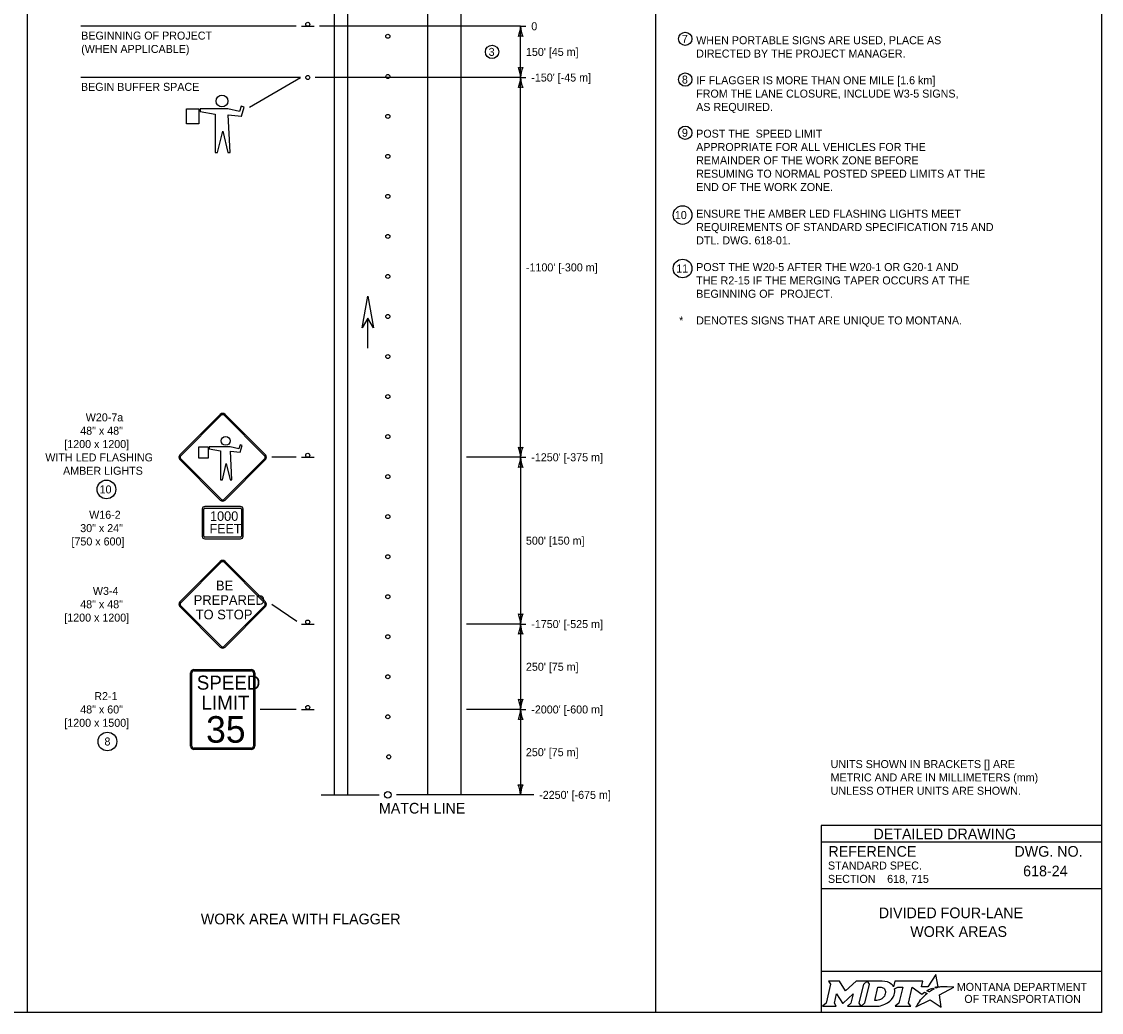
# Model space of a CAD drawing. Extents: x 49991.4 to 50021, y 49987.6 to 50011.4.
# Drawn here: x 50008.66 to 50016.75, y 49987.8 to 49995.22 of the extents above; entities that cross this region are included whole.
import ezdxf

# ---------------------------------------------------------------- set-up
doc = ezdxf.new("R2010")
doc.units = 0
for name, color, linetype in [('Default', 7, 'Continuous'), ('Level 1', 7, 'Continuous'), ('Level 2', 7, 'Continuous'), ('Level 3', 7, 'Continuous'), ('Level 5', 7, 'Continuous'), ('Level 6', 7, 'Continuous')]:
    doc.layers.add(name, color=color, linetype=linetype)

msp = doc.modelspace()

# ---------------------------------------------------------------- linework, layer by layer
at = {"layer": 'Default'}
for points in [[(50014.7056, 49988.0338), (50014.7197, 49988.0104), (50014.6862, 49987.8671), (50014.6605, 49987.8446), (50014.7621, 49987.8446), (50014.7486, 49987.8674), (50014.7648, 49987.9375), (50014.8085, 49987.8685), (50014.8138, 49987.8685), (50014.8889, 49987.938), (50014.8725, 49987.8669), (50014.8478, 49987.8449), (50014.9494, 49987.8449), (50014.9356, 49987.8682), (50014.9688, 49988.0106)], [(50014.9688, 49988.0106), (50014.9941, 49988.0338), (50014.9117, 49988.0338), (50014.8321, 49987.9608), (50014.7876, 49988.0335), (50014.7056, 49988.0338)], [(50015.1077, 49988.0338), (50014.9941, 49988.0338), (50015.0088, 49988.0109), (50014.9749, 49987.8671), (50014.9494, 49987.8449), (50015.06, 49987.8449)], [(50015.5126, 49987.9811), (50015.5023, 49987.9867), (50015.5139, 49987.9895), (50015.5255, 49987.9915), (50015.5081, 49988.0816), (50015.4486, 49987.9903), (50015.4013, 49987.9896), (50015.4116, 49988.0337), (50015.2024, 49988.0338), (50015.1923, 49987.9913), (50015.1865, 49987.9996)], [(50015.1317, 49987.9471), (50015.1305, 49987.939), (50015.1273, 49987.9297), (50015.1231, 49987.9215), (50015.1175, 49987.914), (50015.111, 49987.9071), (50015.1031, 49987.9008), (50015.0948, 49987.8961), (50015.0857, 49987.8922), (50015.0766, 49987.8899), (50015.0674, 49987.889), (50015.0515, 49987.889), (50015.0751, 49987.989), (50015.0911, 49987.989), (50015.0987, 49987.9884), (50015.1063, 49987.9865), (50015.1129, 49987.9835), (50015.119, 49987.9793), (50015.1238, 49987.9743), (50015.1275, 49987.9683), (50015.1302, 49987.9621), (50015.1318, 49987.9547), (50015.1318, 49987.9517), (50015.1317, 49987.9471)], [(50015.1991, 49987.9747), (50015.2237, 49987.9878), (50015.2606, 49987.9878), (50015.232, 49987.8673), (50015.2045, 49987.8446), (50015.3207, 49987.8446), (50015.3037, 49987.8675), (50015.3319, 49987.9877), (50015.4032, 49987.936), (50015.4243, 49987.9511), (50015.444, 49987.9402)], [(50015.3882, 49987.8843), (50015.3729, 49987.8599), (50015.3682, 49987.8524), (50015.3624, 49987.8438), (50015.3601, 49987.8395), (50015.4654, 49987.8926), (50015.5493, 49987.8375), (50015.5362, 49987.9302), (50015.6431, 49987.9886), (50015.5938, 49987.9894), (50015.5637, 49987.9898), (50015.5429, 49987.9901), (50015.5361, 49987.9886), (50015.5312, 49987.9874), (50015.5228, 49987.9851), (50015.5126, 49987.9811)], [(50015.4622, 49987.9535), (50015.4598, 49987.9518), (50015.4415, 49987.9614), (50015.4518, 49987.9671), (50015.4559, 49987.9693), (50015.4645, 49987.9733), (50015.4702, 49987.9759), (50015.4781, 49987.9789), (50015.4854, 49987.9816), (50015.4972, 49987.9742), (50015.4932, 49987.9721), (50015.4886, 49987.9696), (50015.4844, 49987.9674), (50015.4794, 49987.9645), (50015.4775, 49987.9634), (50015.4748, 49987.9618), (50015.4723, 49987.9604), (50015.47, 49987.9588), (50015.4674, 49987.957), (50015.4647, 49987.9552), (50015.4622, 49987.9535)], [(50015.1057, 49987.8522), (50015.1141, 49987.8548), (50015.1271, 49987.8602), (50015.1475, 49987.8712)], [(50015.4021, 49987.9004), (50015.4021, 49987.9004)]]:
    msp.add_lwpolyline(points, dxfattribs=at)
for centre, radius, start, end in [((50015.1308, 49987.9554), 0.0709, 339.53292, 15.85821), ((50015.0868, 49987.9727), 0.1183, 300.91025, 339.13831)]:
    msp.add_arc(centre, radius, start, end, dxfattribs=at)
for centre, major_axis, ratio, start_param, end_param in [((50015.1056, 49987.9864), (0.0834, -0.0037), 0.568097, 0.61298, 1.570796), ((50015.1612, 49987.9937), (0.0361, -0.0295), 0.469099, 1.225588, 1.570796), ((50015.3952, 49987.8923), (-0.00694, -0.00806), 0.008222, 0, 3.137361), ((50015.4119, 49987.9106), (-0.0098, -0.0102), 0.016458, 3.141593, 6.279097), ((50015.4329, 49987.9305), (-0.0112, -0.0097), 0.021651, 3.157348, 6.283185), ((50015.0603, 49987.9932), (0, 0.1484), 0.987302, 3.139398, 3.456847)]:
    msp.add_ellipse(centre, major_axis=major_axis, ratio=ratio, start_param=start_param, end_param=end_param, dxfattribs=at)
at = {"layer": 'Level 1'}
for p, q in [((50011.0016, 49989.429), (50011.0016, 49998.194)), ((50011.1016, 49989.429), (50011.1016, 49998.194)), ((50011.7016, 49989.429), (50011.7016, 49998.194)), ((50011.9516, 49989.429), (50011.9516, 49998.194)), ((50010.7536, 49995.189), (50010.8496, 49995.189)), ((50010.3015, 49994.5895), (50010.2888, 49994.5499)), ((50010.3235, 49994.584), (50010.3015, 49994.5895)), ((50010.3035, 49994.5152), (50010.3235, 49994.584)), ((50009.8929, 49994.4581), (50009.8929, 49994.5706)), ((50009.8929, 49994.5706), (50009.9848, 49994.5706)), ((50009.9848, 49994.5706), (50009.9848, 49994.4581)), ((50010.202, 49994.5699), (50009.9951, 49994.5699)), ((50009.9951, 49994.5699), (50009.9951, 49994.5513)), ((50009.9951, 49994.5513), (50010.1076, 49994.5291)), ((50010.1076, 49994.5291), (50010.1076, 49994.2428)), ((50010.2888, 49994.5499), (50010.202, 49994.5699)), ((50010.2207, 49994.2428), (50010.2059, 49994.5262)), ((50010.2059, 49994.5262), (50010.3035, 49994.5152)), ((50009.9848, 49994.4581), (50009.8929, 49994.4581)), ((50010.1258, 49994.2428), (50010.1641, 49994.4041)), ((50010.1641, 49994.4041), (50010.2024, 49994.2428)), ((50010.1076, 49994.2428), (50010.1258, 49994.2428)), ((50010.2024, 49994.2428), (50010.2207, 49994.2428)), ((50011.2516, 49992.776), (50011.2516, 49993.0019)), ((50011.2519, 49992.776), (50011.2519, 49993.0019)), ((50010.1459, 49992.2807), (50009.8418, 49991.9767)), ((50010.1529, 49992.2737), (50009.8489, 49991.9696)), ((50010.4782, 49991.9696), (50010.1742, 49992.2737)), ((50010.4853, 49991.9767), (50010.1812, 49992.2807)), ((50009.9852, 49991.953), (50009.9852, 49992.038)), ((50009.9852, 49992.038), (50010.0547, 49992.038)), ((50010.0547, 49992.038), (50010.0547, 49991.953)), ((50010.219, 49992.0376), (50010.0625, 49992.0376)), ((50010.0625, 49992.0376), (50010.0625, 49992.0235)), ((50010.0625, 49992.0235), (50010.1475, 49992.0067)), ((50010.1475, 49992.0067), (50010.1475, 49991.7902)), ((50010.2846, 49992.0224), (50010.219, 49992.0376)), ((50010.233, 49991.7902), (50010.2218, 49992.0045)), ((50010.2218, 49992.0045), (50010.2957, 49991.9962)), ((50010.2942, 49992.0524), (50010.2846, 49992.0224)), ((50010.3108, 49992.0482), (50010.2942, 49992.0524)), ((50010.2957, 49991.9962), (50010.3108, 49992.0482)), ((50009.8418, 49991.9413), (50010.1459, 49991.6373)), ((50009.8489, 49991.9484), (50010.1529, 49991.6443)), ((50010.0547, 49991.953), (50009.9852, 49991.953)), ((50010.1613, 49991.7902), (50010.1902, 49991.9122)), ((50010.1742, 49991.6443), (50010.4782, 49991.9484)), ((50010.1812, 49991.6373), (50010.4853, 49991.9413)), ((50010.1902, 49991.9122), (50010.2192, 49991.7902)), ((50010.7534, 49991.959), (50010.8494, 49991.959)), ((50010.1475, 49991.7902), (50010.1613, 49991.7902)), ((50010.2192, 49991.7902), (50010.233, 49991.7902)), ((50010.2976, 49991.5899), (50010.0295, 49991.5899)), ((50010.0103, 49991.5698), (50010.0103, 49991.3682)), ((50010.0231, 49991.3682), (50010.0231, 49991.5698)), ((50010.0295, 49991.5765), (50010.2976, 49991.5765)), ((50010.304, 49991.5698), (50010.304, 49991.3682)), ((50010.3168, 49991.3682), (50010.3168, 49991.5698)), ((50010.2976, 49991.3615), (50010.0295, 49991.3615)), ((50010.0295, 49991.348), (50010.2976, 49991.348)), ((50009.8418, 49990.875), (50010.1459, 49991.179)), ((50009.8489, 49990.8679), (50010.1529, 49991.172)), ((50010.1742, 49991.172), (50010.4782, 49990.8679)), ((50010.1812, 49991.179), (50010.4853, 49990.875)), ((50010.1459, 49990.5356), (50009.8418, 49990.8396)), ((50010.1529, 49990.5426), (50009.8489, 49990.8467)), ((50010.4782, 49990.8467), (50010.1742, 49990.5426)), ((50010.4853, 49990.8396), (50010.1812, 49990.5356)), ((50010.7534, 49990.709), (50010.8494, 49990.709)), ((50009.9236, 49989.794), (50009.9236, 49990.344)), ((50009.9336, 49989.794), (50009.9336, 49990.344)), ((50009.9486, 49990.369), (50010.3786, 49990.369)), ((50009.9486, 49990.359), (50010.3786, 49990.359)), ((50010.3936, 49990.344), (50010.3936, 49989.794)), ((50010.4036, 49990.344), (50010.4036, 49989.794)), ((50010.7536, 49990.069), (50010.8496, 49990.069)), ((50010.3786, 49989.779), (50009.9486, 49989.779)), ((50010.3786, 49989.769), (50009.9486, 49989.769))]:
    msp.add_line(p, q, dxfattribs=at)
for points in [[(49999.3835, 49998.9992), (50016.7501, 49998.9992), (50016.7501, 49987.7988), (49999.3835, 49987.7988)], [(50011.2099, 49992.9296), (50011.2516, 49993.1661), (50011.2935, 49992.9296), (50011.2516, 49993.0018)]]:
    msp.add_lwpolyline(points, close=True, dxfattribs=at)
for points in [[(50010.3014, 49994.5893), (50010.3016, 49994.5895)], [(50010.3029, 49994.5153), (50010.3038, 49994.5164)], [(50009.9844, 49994.4581), (50009.9848, 49994.4585)], [(50010.2941, 49992.0522), (50010.2942, 49992.0524)], [(50010.2952, 49991.9963), (50010.2959, 49991.9971)], [(50010.0544, 49991.953), (50010.0547, 49991.9533)]]:
    msp.add_lwpolyline(points, dxfattribs=at)
for centre, radius in [((50010.8016, 49995.2042), 0.0152), ((50011.4016, 49995.114), 0.015), ((50011.4021, 49994.8126), 0.015), ((50010.8016, 49994.805), 0.0152), ((50010.1584, 49994.6287), 0.0442), ((50011.4016, 49994.514), 0.015), ((50011.4016, 49994.214), 0.015), ((50011.4016, 49993.914), 0.015), ((50011.4016, 49993.614), 0.015), ((50011.4016, 49993.314), 0.015), ((50011.4016, 49993.014), 0.015), ((50011.4016, 49992.714), 0.015), ((50011.4016, 49992.414), 0.015), ((50010.186, 49992.082), 0.0334), ((50011.4016, 49992.114), 0.015), ((50010.8014, 49991.9742), 0.0152), ((50011.4016, 49991.814), 0.015), ((50011.4016, 49991.514), 0.015), ((50011.4016, 49991.214), 0.015), ((50011.4016, 49990.914), 0.015), ((50010.8014, 49990.7242), 0.0152), ((50011.4016, 49990.614), 0.015), ((50011.4016, 49990.314), 0.015), ((50010.8016, 49990.0842), 0.0152), ((50011.4016, 49990.014), 0.015), ((50011.4086, 49989.714), 0.015), ((50011.4016, 49989.429), 0.025)]:
    msp.add_circle(centre, radius, dxfattribs=at)
for centre, radius, start, end in [((50010.1636, 49992.2631), 0.025, 45, 135), ((50010.1636, 49992.2631), 0.015, 45, 135), ((50009.8595, 49991.959), 0.025, 135, 225), ((50009.8595, 49991.959), 0.015, 135, 225), ((50010.4676, 49991.959), 0.015, 315, 45.00024), ((50010.4676, 49991.959), 0.025, 315, 45.00024), ((50010.1636, 49991.6549), 0.025, 225, 314.99957), ((50010.1636, 49991.6549), 0.015, 225, 314.99957), ((50010.1635, 49991.1614), 0.025, 45, 135), ((50010.1635, 49991.1614), 0.015, 45, 135), ((50009.8595, 49990.8574), 0.025, 134.99976, 225), ((50009.8595, 49990.8574), 0.015, 134.99976, 225), ((50010.4676, 49990.8574), 0.015, 315, 45), ((50010.4676, 49990.8574), 0.025, 315, 45), ((50010.1635, 49990.5533), 0.025, 225.00043, 315), ((50010.1635, 49990.5533), 0.015, 225.00043, 315), ((50009.9486, 49990.344), 0.025, 90, 180), ((50009.9486, 49990.344), 0.015, 90, 180), ((50010.3786, 49990.344), 0.025, 0, 90), ((50010.3786, 49990.344), 0.015, 0, 90), ((50009.9486, 49989.794), 0.025, 180, 270), ((50009.9486, 49989.794), 0.015, 180, 270), ((50010.3786, 49989.794), 0.025, 270, 0), ((50010.3786, 49989.794), 0.015, 270, 0)]:
    msp.add_arc(centre, radius, start, end, dxfattribs=at)
for centre, major_axis, start_param, end_param in [((50010.0295, 49991.5698), (0, 0.0202), 0, 1.570796), ((50010.2976, 49991.5698), (0, 0.0202), 4.712389, 6.283185), ((50010.0295, 49991.5698), (0, 0.00672), 0, 1.570796), ((50010.2976, 49991.5698), (0, 0.00672), 4.712389, 6.283185), ((50010.0295, 49991.3682), (0, -0.0202), 4.712389, 6.283185), ((50010.0295, 49991.3682), (0, -0.00672), 4.712389, 6.283185), ((50010.2976, 49991.3682), (0, -0.00672), 0, 1.570796), ((50010.2976, 49991.3682), (0, -0.0202), 0, 1.570796)]:
    msp.add_ellipse(centre, major_axis=major_axis, ratio=0.95, start_param=start_param, end_param=end_param, dxfattribs=at)
at = {"layer": 'Level 2'}
for centre, radius in [((50013.631, 49995.0948), 0.05), ((50012.1824, 49994.997), 0.05), ((50013.631, 49994.7897), 0.05), ((50013.631, 49994.3911), 0.05), ((50013.611, 49993.7743), 0.07), ((50013.611, 49993.3737), 0.07), ((50009.2924, 49991.7181), 0.07), ((50009.2996, 49989.829), 0.07)]:
    msp.add_circle(centre, radius, dxfattribs=at)
at = {"layer": 'Level 3'}
for p, q in [((50008.6982, 49998.9992), (50008.6982, 49987.7988)), ((50013.4076, 49998.9992), (50013.4076, 49987.7988)), ((50010.7136, 49995.189), (50009.1014, 49995.189)), ((50012.3968, 49995.189), (50010.8896, 49995.189)), ((50012.3968, 49994.805), (50012.3968, 49995.189)), ((50012.3968, 49995.189), (50012.4368, 49995.189)), ((50010.7463, 49994.805), (50009.1014, 49994.805)), ((50010.3635, 49994.584), (50010.7463, 49994.805)), ((50012.3968, 49994.805), (50010.8568, 49994.805)), ((50012.3968, 49991.959), (50012.3968, 49994.805)), ((50012.3968, 49994.805), (50012.4368, 49994.805)), ((50010.7134, 49991.959), (50010.5326, 49991.959)), ((50012.3968, 49991.959), (50011.9916, 49991.959)), ((50012.3968, 49991.959), (50012.3968, 49990.709)), ((50012.3968, 49991.959), (50012.4368, 49991.959)), ((50010.5326, 49990.8574), (50010.7202, 49990.7313)), ((50012.3968, 49990.709), (50011.9916, 49990.709)), ((50012.3968, 49990.709), (50012.3968, 49990.069)), ((50012.3968, 49990.709), (50012.4368, 49990.709)), ((50010.7136, 49990.069), (50010.4436, 49990.069)), ((50012.3968, 49990.069), (50011.9916, 49990.069)), ((50012.3968, 49990.069), (50012.396, 49989.429)), ((50012.3968, 49990.069), (50012.4368, 49990.069))]:
    msp.add_line(p, q, dxfattribs=at)
for centre, radius, start, end in [((50012.1641, 49995.2005), 0.233, 337.92284, 357.17269), ((50012.6189, 49995.1982), 0.2223, 182.36048, 202.54399), ((50012.3968, 49995.0608), 0.0548, 72.13882, 107.86118), ((50012.3968, 49994.9332), 0.0548, 252.13882, 287.86118), ((50012.1641, 49994.7935), 0.233, 2.82731, 22.07716), ((50012.6189, 49994.7958), 0.2223, 157.45601, 177.63952), ((50012.1641, 49994.8165), 0.233, 337.92284, 357.17269), ((50012.6189, 49994.8142), 0.2223, 182.36048, 202.54399), ((50012.3968, 49994.6768), 0.0548, 72.13882, 107.86118), ((50012.1747, 49991.9498), 0.2223, 2.36048, 22.54399), ((50012.3968, 49992.0872), 0.0548, 252.13882, 287.86118), ((50012.6295, 49991.9475), 0.233, 157.92284, 177.17269), ((50012.1747, 49991.9682), 0.2223, 337.45601, 357.63952), ((50012.6295, 49991.9705), 0.233, 182.82731, 202.07716), ((50012.3968, 49991.8308), 0.0548, 72.13882, 107.86118), ((50012.3968, 49990.8372), 0.0548, 252.13882, 287.86118), ((50012.1641, 49990.6975), 0.233, 2.82731, 22.07716), ((50012.6189, 49990.6998), 0.2223, 157.45601, 177.63952), ((50012.1747, 49990.7182), 0.2223, 337.45601, 357.63952), ((50012.6295, 49990.7205), 0.233, 182.82731, 202.07716), ((50012.3968, 49990.5808), 0.0548, 72.13882, 107.86118), ((50012.3968, 49990.1972), 0.0548, 252.13882, 287.86118), ((50012.1641, 49990.0575), 0.233, 2.82731, 22.07716), ((50012.6189, 49990.0598), 0.2223, 157.45601, 177.63952), ((50012.1747, 49990.0782), 0.2223, 337.45601, 357.63952), ((50012.6295, 49990.0805), 0.233, 182.82731, 202.07716), ((50012.3968, 49989.9408), 0.0548, 72.13882, 107.86118), ((50012.396, 49989.5572), 0.0548, 252.13882, 287.86118), ((50012.1633, 49989.4175), 0.233, 2.82731, 22.07716), ((50012.6182, 49989.4198), 0.2223, 157.45601, 177.63952)]:
    msp.add_arc(centre, radius, start, end, dxfattribs=at)
at = {"layer": 'Level 5'}
for p, q in [((50016.7501, 49989.1988), (50014.6501, 49989.1988)), ((50014.6501, 49989.1988), (50014.6501, 49987.7988)), ((50016.7501, 49989.0738), (50014.6501, 49989.0738)), ((50016.3862, 49988.8587), (50016.3862, 49988.8587)), ((50015.1444, 49988.7993), (50015.1444, 49988.7993)), ((50016.7501, 49988.7238), (50014.6501, 49988.7238)), ((50015.7001, 49988.4747), (50015.7001, 49988.4747)), ((50016.7501, 49988.1057), (50014.6501, 49988.1057))]:
    msp.add_line(p, q, dxfattribs=at)
at = {"layer": 'Level 6'}
for p, q in [((50010.9016, 49989.429), (50011.3366, 49989.429)), ((50012.496, 49989.429), (50011.4666, 49989.429))]:
    msp.add_line(p, q, dxfattribs=at)

# ---------------------------------------------------------------- texts
at = {"layer": 'Default'}
for s, p in [('MONTANA DEPARTMENT', (50015.6663, 49987.96)), ('OF TRANSPORTATION', (50015.7225, 49987.87))]:
    msp.add_text(s, height=0.06, dxfattribs=at).set_placement(p)
at = {"layer": 'Level 1'}
for s, height, p in [('1000', 0.07124, (50010.0685, 49991.4824)), ('FEET', 0.06989, (50010.0655, 49991.3883)), ('BE', 0.0725, (50010.1132, 49990.9618)), ('PREPARED', 0.0725, (50009.9463, 49990.853)), ('TO STOP', 0.0725, (50009.9611, 49990.7443)), ('SPEED', 0.10512, (50009.9698, 49990.2174)), ('LIMIT', 0.10512, (50010.0052, 49990.0673)), ('35', 0.19892, (50010.0392, 49989.82))]:
    msp.add_text(s, height=height, dxfattribs=at).set_placement(p)
at = {"layer": 'Level 2'}
for s, height, p in [('BEGINNING OF PROJECT', 0.06, (50009.1033, 49995.089)), ('0', 0.06, (50012.4768, 49995.159)), ('7', 0.06, (50013.6058, 49995.0648)), ('WHEN PORTABLE SIGNS ARE USED, PLACE AS', 0.06, (50013.7128, 49995.0544)), ('(WHEN APPLICABLE)', 0.06, (50009.1033, 49994.989)), ('3', 0.06, (50012.1572, 49994.967)), ("150' [45 m]", 0.06, (50012.4368, 49994.967)), ('DIRECTED BY THE PROJECT MANAGER.', 0.06, (50013.7128, 49994.9544)), ("-150' [-45 m]", 0.06, (50012.4768, 49994.775)), ('BEGIN BUFFER SPACE', 0.06, (50009.1014, 49994.705)), ('8', 0.06, (50013.6058, 49994.7597)), ('IF FLAGGER IS MORE THAN ONE MILE [1.6 km]', 0.06, (50013.7128, 49994.7544)), ('FROM THE LANE CLOSURE, INCLUDE W3-5 SIGNS,', 0.06, (50013.7128, 49994.6544)), ('AS REQUIRED.', 0.06, (50013.7128, 49994.5544)), ('9', 0.06, (50013.6056, 49994.3611)), ('POST THE  SPEED LIMIT', 0.06, (50013.7128, 49994.3544)), ('APPROPRIATE FOR ALL VEHICLES FOR THE ', 0.06, (50013.7128, 49994.2544)), ('REMAINDER OF THE WORK ZONE BEFORE', 0.06, (50013.7128, 49994.1544)), ('RESUMING TO NORMAL POSTED SPEED LIMITS AT THE', 0.06, (50013.7128, 49994.0544)), ('END OF THE WORK ZONE.', 0.06, (50013.7128, 49993.9544)), ('10', 0.06, (50013.5528, 49993.7443)), ('ENSURE THE AMBER LED FLASHING LIGHTS MEET', 0.06, (50013.7128, 49993.7544)), ('REQUIREMENTS OF STANDARD SPECIFICATION 715 AND ', 0.06, (50013.7128, 49993.6544)), ('DTL. DWG. 618-01.', 0.06, (50013.7128, 49993.5544)), ("-1100' [-300 m]", 0.06, (50012.4368, 49993.352)), ('11', 0.06, (50013.5631, 49993.3437)), ('POST THE W20-5 AFTER THE W20-1 OR G20-1 AND', 0.06, (50013.7128, 49993.3544)), ('THE R2-15 IF THE MERGING TAPER OCCURS AT THE', 0.06, (50013.7128, 49993.2544)), ('BEGINNING OF  PROJECT.', 0.06, (50013.7128, 49993.1544)), ('*', 0.06, (50013.5849, 49992.9544)), ('DENOTES SIGNS THAT ARE UNIQUE TO MONTANA.', 0.06, (50013.7128, 49992.9544)), ('W20-7a', 0.06, (50009.1373, 49992.2281)), ('48" x 48"', 0.06, (50009.0959, 49992.1281)), ('[1200 x 1200]', 0.06, (50008.9764, 49992.0281)), ("-1250' [-375 m]", 0.06, (50012.4768, 49991.929)), ('WITH LED FLASHING', 0.06, (50008.8342, 49991.9281)), ('AMBER LIGHTS', 0.06, (50008.9674, 49991.8281)), ('10', 0.06, (50009.2411, 49991.6881)), ('W16-2', 0.06, (50009.1628, 49991.4981)), ('30" x 24"', 0.06, (50009.0959, 49991.3981)), ('[750 x 600]', 0.06, (50009.0303, 49991.2981)), ("500' [150 m]", 0.06, (50012.4368, 49991.304)), ('W3-4', 0.06, (50009.1909, 49990.9274)), ('48" x 48"', 0.06, (50009.0959, 49990.8274)), ('[1200 x 1200]', 0.06, (50008.9764, 49990.7274)), ("-1750' [-525 m]", 0.06, (50012.4768, 49990.679)), ("250' [75 m]", 0.06, (50012.4368, 49990.359)), ('R2-1', 0.06, (50009.2014, 49990.139)), ('48" x 60"', 0.06, (50009.0959, 49990.039)), ("-2000' [-600 m]", 0.06, (50012.4768, 49990.039)), ('[1200 x 1500]', 0.06, (50008.9764, 49989.939)), ('8', 0.06, (50009.2774, 49989.799)), ("250' [75 m]", 0.06, (50012.4364, 49989.719)), ('UNITS SHOWN IN BRACKETS [] ARE ', 0.06, (50014.7204, 49989.6298)), ('METRIC AND ARE IN MILLIMETERS (mm) ', 0.06, (50014.7204, 49989.5298)), ('UNLESS OTHER UNITS ARE SHOWN.', 0.06, (50014.7204, 49989.4298)), ("-2250' [-675 m]", 0.06, (50012.536, 49989.399)), ('MATCH LINE', 0.08, (50011.3346, 49989.289)), ('618-24', 0.08, (50016.1636, 49988.8187)), ('618, 715', 0.06, (50015.1444, 49988.7693)), ('WORK AREA WITH FLAGGER', 0.08, (50009.9996, 49988.4588)), ('DIVIDED FOUR-LANE', 0.08, (50015.0815, 49988.5047)), ('WORK AREAS', 0.08, (50015.3174, 49988.3647))]:
    msp.add_text(s, height=height, dxfattribs=at).set_placement(p)
at = {"layer": 'Level 5'}
for s, height, p in [('DETAILED DRAWING', 0.0799, (50015.0418, 49989.0963)), ('REFERENCE', 0.08, (50014.7037, 49988.9654)), ('DWG. NO.', 0.08, (50016.0979, 49988.9654)), ('STANDARD SPEC.', 0.06, (50014.7004, 49988.8694)), ('SECTION', 0.06, (50014.7004, 49988.7694))]:
    msp.add_text(s, height=height, dxfattribs=at).set_placement(p)

doc.saveas('drawing.dxf')
